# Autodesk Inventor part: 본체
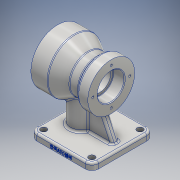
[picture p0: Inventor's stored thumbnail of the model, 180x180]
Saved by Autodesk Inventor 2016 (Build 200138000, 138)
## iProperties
Created: 2019-01
Part Number: 본체
Material: 알루미늄 6061
Document SubType Name: Modeling
Designer: USER
Density: 2.7 g/cm^3
Appearance: 알루미늄 - 평지
Mass: 898.787 g
Surface Area: 605.063 cm^2
Volume: 332.884 cm^3
Author: USER
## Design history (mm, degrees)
sketch "스케치1"
  geometry: L1 (0, 0)-(-80, 0); L2 (0, 26)-(-19, 26); L3 (-20, 25)-(-20, 16); L4 (-20, 16)-(-63, 16); L5 (-63, 16)-(-63, 19.4); L6 (-63.6, 20)-(-80, 20); L7 (-80, 20)-(-80, 35); L8 (0, 26)-(0, 40); L9 (0, 40)-(-25, 40); L10 (-80, 35)-(-65, 35); L11 (-45.785, 28)-(-59.126, 28); L12 (-25, 40)-(-45.785, 28); L13 (-65, 35)-(-59.126, 28); A1 r 1 centre (-19, 25) between (-19, 26) and (-20, 25); A2 r 0.6 centre (-63.6, 19.4) between (-63, 19.4) and (-63.6, 20); 4 further points
  constraints: 26 end point, 6 perpendicular, 4 horizontal, 4 point on circle, 4 point on line, 4 tangent, 2 centre point, 2 midpoint, 2 vertical alignment, 1 vertical
  dimensions: "d0" = 80 distance of L1.start L1.end; "d1" = 25 distance of L8.end L9.end; "d2" = 80 diameter of L9 L1; "d3" = 52 diameter of L2 L1; "d4" = 32 diameter of L4 L1; "d5" = 40 diameter of L6 L1; "d6" = 15 distance of L7.end L10.end; "d7" = 70 diameter of L10 L1; "d8" = 20 distance of L2.start point (-20, 26); "d9" = 17 distance of point (-63, 20) L6.end; "d10" = 56 diameter of L11 L1; "d11" = 30 deg angle of L12 L11; "d12" = 50 deg angle of L13 L11; "d60" = 1 radius of A1; "d61" = 0.6 radius of A2
revolve "회전1" sketch "스케치1" stored, may be unused: angle "d13" = 90 deg
node "작업 평면1"
sketch "스케치2"
  geometry: L1 (5, 46)-(97, 46); L2 (97, 46)-(97, -46); L3 (97, -46)-(5, -46); L4 (5, -46)-(5, 46); L5 (5, 46)-(97, -46); L6 (97, 46)-(5, -46); L7 (0, 40)-(0, -40) reference; 5 further points
  constraints: 12 end point, 6 midpoint, 2 parallel, 1 horizontal, 1 horizontal alignment, 1 perpendicular
  dimensions: "d15" = 92 distance of L1.start L1.end; "d16" = 92 distance of L1.end L2.end; "d67" = 5 distance between parallel lines of L4 L7
extrude "돌출1" join sketch "스케치2" distance "d17" = 10; taper "d18" = 0 deg
sketch "스케치3"
  geometry: C1 r 16 at (35, 0); 1 further point
  constraints: 1 centre point, 1 horizontal alignment
  dimensions: "d19" = 35 distance of C1.centre point (0, 0); "d20" = 32 diameter of C1
extrude "돌출2" join sketch "스케치3" stored distance "d21" = 10; taper "d22" = 0 deg
sketch "스케치4"
  geometry: L1 (-87, -70)-(-70.679, -35); L2 (-97, -80)-(-97, -70) reference; L3 (-97, -70)-(-5, -70) reference; L4 (-80, -35)-(-65, -35) reference; 1 further point
  constraints: 2 end point, 2 point on line
  dimensions: "d23" = 10 distance from line of L2 L1.start; "d24" = 25 deg angle of L1 L2
feature "리브1" sketch "스케치4" dims "d25" = 1, "d26" = 10, "d27" = 0, "d28" = 0, "d29" = 1, "d30" = 1
fillet "모깎기1" dims "d31" = 10
sketch "스케치5"
  geometry: C1 r 4.5 at (15, 36); C2 r 4.5 at (87, 36); A1 r 10 centre (15, 36) between (15, 46) and (5, 36) reference; A2 r 10 centre (87, 36) between (97, 36) and (87, 46) reference; 1 further point
  constraints: 2 centre point, 1 coincident, 1 concentric
  dimensions: "d32" = 9 diameter of C1; "d33" = 9 diameter of C2
extrude "돌출3" cut sketch "스케치5" distance "d34" = 10; taper "d35" = 0 deg
sketch "스케치6" dims "d36" = 66
  geometry: L1 (0, 0)-(33, 0); 5 further points
  constraints: 2 coincident, 2 end point, 1 horizontal, 1 horizontal alignment, 7 other
  dimensions: "d39" = 360 deg dimension on point (0, 0) L1.end (derived)
hole "구멍1" sketch "스케치6" at (33, 0), (0, -33), (0, 33), (-33, 0) diameter "d41" = 3.242; stored, may be unused: countersink angle "d45" = 90 deg, drill point angle "d47" = 118 deg; dims "d42" = 9, "d43" = 4, "d44" = 2, "d46" = 11
sketch "스케치7" dims "d48" = 55
  geometry: L1 (0, 0)-(-27.5, 0); 5 further points
  constraints: 2 coincident, 2 end point, 1 horizontal, 1 horizontal alignment, 7 other
  dimensions: "d51" = 360 deg dimension on point (0, 0) L1.end (derived)
hole "구멍2" sketch "스케치7" at (-27.5, 0), (0, -27.5), (27.5, 0), (0, 27.5) diameter "d53" = 3.242; stored, may be unused: countersink angle "d57" = 90 deg, drill point angle "d59" = 118 deg; dims "d54" = 9, "d55" = 4, "d56" = 2, "d58" = 11
chamfer "모따기1" distance "d62" = 1; stored, may be unused: second distance "d63" = 2, angle "d64" = 45 deg
fillet "모깎기2" dims "d65" = 3
fillet "모깎기3" dims "d66" = 3
sketch "스케치8"
  geometry: L1 (72, 0)-(0, 0) reference; L2 (-10, 7)-(-10, 0) reference; 2 further points
  constraints: 1 other
  dimensions: "d68" = 4 distance from line of L1 point (36, 4); "d69" = 46 distance from line of L2 point (36, 4)
feature "엠보싱1" sketch "스케치8" dims "d0" = 80, "d1" = 25, "d2" = 80, "d3" = 52, "d4" = 32, "d5" = 40, "d6" = 15, "d7" = 70, "d8" = 20, "d9" = 17, "d10" = 56, "d11" = 30 deg, "d12" = 50 deg, "d60" = 1, "d61" = 0.6, "d70" = 0.5, "d71" = 0
fillet "모깎기4" dims "d72" = 3
node "솔리드1"
mirror "대칭1"
